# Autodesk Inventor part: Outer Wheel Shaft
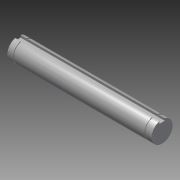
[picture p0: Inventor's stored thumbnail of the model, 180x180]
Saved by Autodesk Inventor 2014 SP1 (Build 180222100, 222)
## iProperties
Created: 2014-07
Part Number: Outer Wheel Shaft
Material: Steel
Document SubType Name: Modeling
Designer: Michael
Density: 7.85 g/cm^3
Appearance: Steel
Mass: 82.9474 g
Surface Area: 39.9825 cm^2
Volume: 10.5666 cm^3
Author: Michael
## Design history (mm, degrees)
sketch "Sketch1"
  geometry: L1 (-43.472, -6.35)-(43.472, -6.35); L2 (43.472, -6.35)-(43.472, 6.35); L3 (43.472, 6.35)-(-43.472, 6.35); L4 (-43.472, 6.35)-(-43.472, -6.35); L5 (-38.71, -6.35)-(38.71, -6.35); L6 (38.71, -6.35)-(38.71, 6.35); L7 (38.71, 6.35)-(-38.71, 6.35); L8 (-38.71, 6.35)-(-38.71, -6.35); L9 (40.122, 6.35)-(39.106, 6.35); L10 (39.106, 6.35)-(39.106, 5.969); L11 (39.106, 5.969)-(40.122, 5.969); L12 (40.122, 5.969)-(40.122, 6.35); L13 (-39.106, 6.35)-(-40.122, 6.35); L14 (-40.122, 6.35)-(-40.122, 5.969); L15 (-40.122, 5.969)-(-39.106, 5.969); L16 (-39.106, 5.969)-(-39.106, 6.35); L17 (-43.472, 0)-(43.472, 0); 2 further points
  constraints: 34 end point, 8 parallel, 5 perpendicular, 4 horizontal, 4 point on line, 3 midpoint, 1 horizontal alignment, 1 vertical alignment
  dimensions: "d1" = 77.4192 distance between parallel lines of L6 L8; "d2" = 12.7 distance between parallel lines of L1 L3; "d3" = 1.016 distance between parallel lines of L12 L10; "d4" = 5.969 distance from line of L17.end L11; "d5" = 0.39687 distance between parallel lines of L6 L10; "d6" = 4.7625 distance between parallel lines of L4 L8; "d8" = 5.969 distance from line of point (0, 0) L15; "d9" = 1.016 distance between parallel lines of L16 L14; "d10" = 0.39687 distance between parallel lines of L8 L16 (= d5); "d16" = 4.7625 distance between parallel lines of L2 L6 (= d6)
revolve "Revolution1" sketch "Sketch1" stored, may be unused: angle "d11" = 90 deg
sketch "Sketch2"
  geometry: L1 (1.587, 7.938)-(-1.587, 7.938); L2 (-1.587, 7.938)-(-1.587, 4.762); L3 (-1.587, 4.762)-(1.587, 4.762); L4 (1.587, 4.762)-(1.587, 7.938); L5 (1.587, 7.938)-(-1.587, 4.762); L6 (-1.587, 7.938)-(1.587, 4.762); 3 further points
  constraints: 12 end point, 3 midpoint, 2 parallel, 2 vertical alignment, 1 horizontal, 1 perpendicular, 1 other
  dimensions: "d12" = 3.175 distance of L3.end L2.end; "d13" = 3.175 distance of L2.end L1.end
extrude "Extrusion1" cut sketch "Sketch2" stored distance "d14" = 25.4; taper "d15" = 0 deg
body "Solid1"
